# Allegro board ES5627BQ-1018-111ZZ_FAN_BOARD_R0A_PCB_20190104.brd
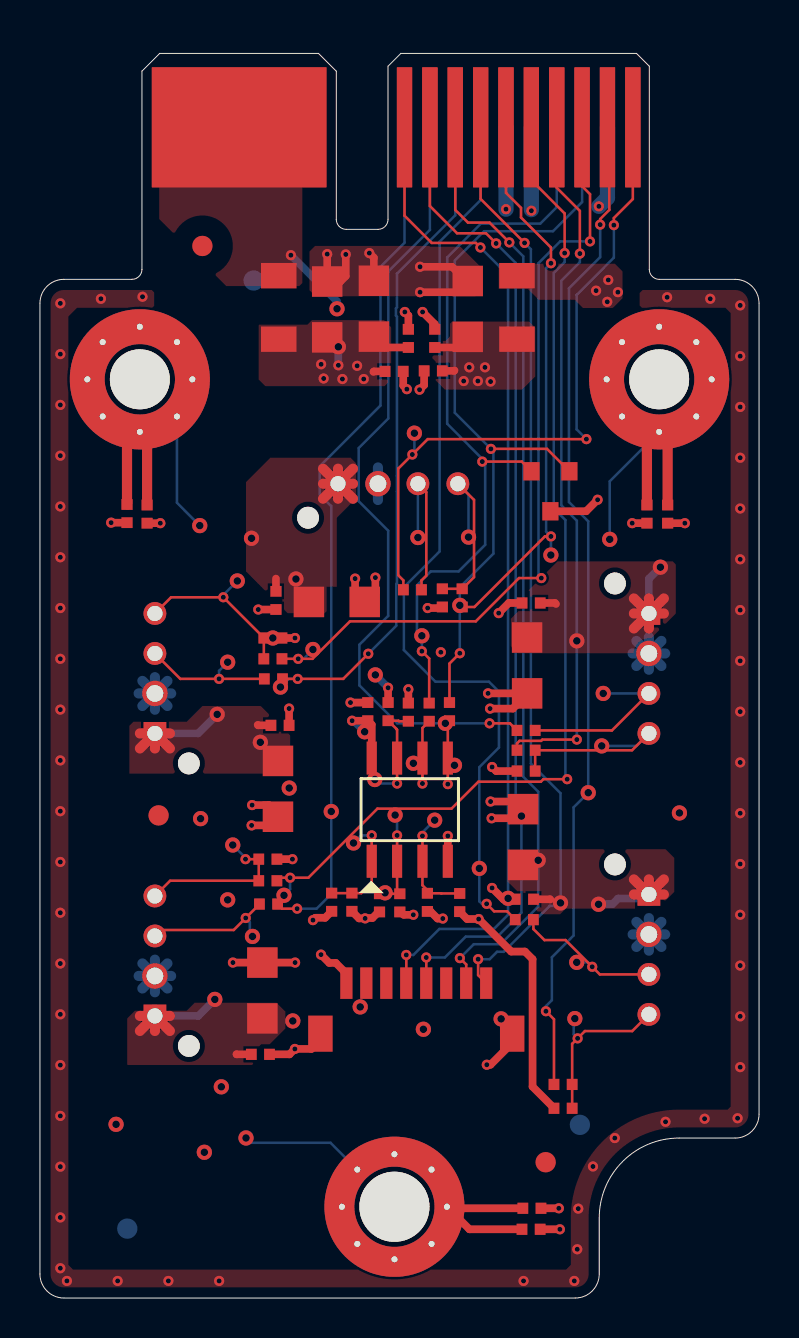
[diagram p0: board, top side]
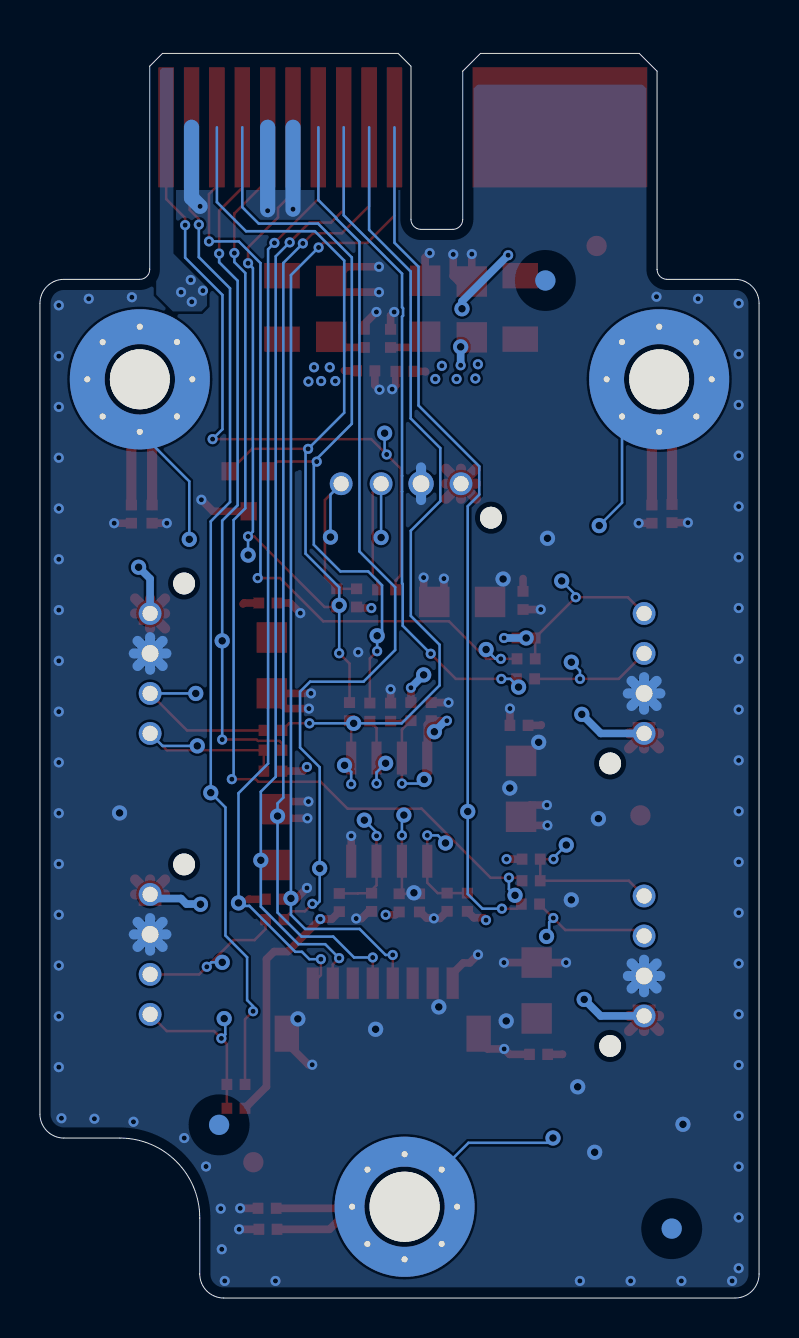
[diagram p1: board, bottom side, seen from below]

Outline 36 x 62.25 mm; copper layers: TOP, V2, G3, BOTTOM. Coordinates in mm from the lower left corner of the outline.
Outline path: 5.1,51.45 5.11,51.45 ; 5.11,51.45 arc(4.96,51.1) 4.61,50.95 1.2,50.95 arc(0.35,50.6) 0,49.75 0,1.2 arc(0.35,0.35) 1.2,0 26.8,0 arc(27.65,0.35) 28,1.2 28,4 arc(29.17,6.83) 32,8 34.8,8 arc(35.65,8.35) 36,9.2 36,49.75 arc(35.65,50.6) 34.8,50.95 31.01,50.95 arc(30.65,51.1) 30.51,51.45 30.51,61.61 29.87,62.25 18.06,62.25 17.43,61.61 17.43,53.95 arc(17.28,53.6) 16.93,53.45 15.33,53.45 arc(14.98,53.6) 14.84,53.95 14.84,61.36 13.95,62.25 6,62.25 5.11,61.36 5.11,51.45

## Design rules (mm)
nets with their own width: min track width 0.381; nets GND VCC3V3 VCC12V VCC_3V3

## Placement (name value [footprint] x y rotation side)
C1  0.1uF  [CC0402]  16.41 29.33 0 top
C2  10uF  [CC1206]  14.38 49.44 180 top
C3  10uF  [CC1206]  16.72 49.48 180 top
C5  0.1uF  [CC0402]  17.73 46.35 90 top
C6  0.1uF  [CC0402]  18.44 48 180 top
C7  10uF  [CC1206]  14.86 34.81 90 top
C9  0.1uF  [CC0402]  11.81 34.89 0 top
C10  10uF  [CC1206]  11.13 15.38 180 top
C12  0.1uF  [CC0402]  11.04 12.19 90 top
C13  10uF  [CC1206]  24.39 31.64 0 top
C15  0.1uF  [CC0402]  24.59 34.76 270 top
C16  10uF  [CC1206]  11.92 25.47 0 top
C18  0.1uF  [CC0402]  12.02 28.64 90 top
C19  10uF  [CC1206]  24.18 23.05 180 top
C21  0.1uF  [CC0402]  24.25 19.94 270 top
C22  10uF  [CC1206]  21.42 49.47 180 top
C25  0.1uF  [CC0402]  19.77 48 180 top
C26  0.1uF  [CC0402]  19.69 46.37 270 top
H1  SKREW 3mm  [MTH_276C118D_8DP_OSP]  31 45.95 0 top
H2  SKREW 3mm  [MTH_276C118D_8DP_OSP]  5 45.95 0 top
H3  SKREW 3.5mm  [MTH_276C138D_8DP_OSP]  17.75 4.56 0 top
J2  1-2232826-4  [CONN_2D_1X4DP_10D32W7D1L]  30.49 17.19 90 top
J3  1-2232826-4  [CONN_2D_1X4DP_10D32W7D1L]  5.75 31.24 270 top
J4  1-2232826-4  [CONN_2D_1X4DP_10D32W7D1L]  30.49 31.24 90 top
J5  1-2232826-4  [CONN_2D_1X4DP_10D32W7D1L]  5.75 17.11 270 top
J6  1-2232826-4  [CONN_2D_1X4DP_10D32W7D1L]  17.92 40.73 180 top
J7  1WFHK-08T-222  [CONN_1D_8SP_10W2D9L4D8H]  18.84 15.75 0 top
J8  @C214B5-100A  [GOLD_FINGER_1D27_10X2SP]  29.68 58.55 0 top
NOREF  -  []  6 62.25 0 top
NOREF#2  -  []  1.2 50.95 0 top
NOREF#3  -  []  0 0 0 top
NOREF#4  -  []  17.75 4.56 0 top
NOREF#5  -  []  0 0 0 top
NOREF#6  -  []  28 1.2 0 top
NOREF#7  -  [unnamed#2]  25.32 6.79 0 top
NOREF#8  -  [unnamed#2]  8.13 52.62 0 top
NOREF#9  -  []  5 45.95 0 top
NOREF#10  -  []  1.91 1.56 0 top
NOREF#11  -  []  31 45.95 0 top
NOREF#12  -  []  14.84 61.36 0 top
NOREF#13  -  []  31 45.95 0 top
NOREF#14  -  []  15.33 53.45 0 top
NOREF#15  -  []  17.75 4.56 0 top
NOREF#16  -  []  30.51 61.61 0 top
NOREF#17  -  []  36 9.2 0 top
NOREF#18  -  []  17.43 61.61 0 top
NOREF#19  -  []  5.11 61.36 0 top
NOREF#20  -  []  5 45.95 0 top
NOREF#21  -  [unnamed#2]  5.94 24.14 0 top
NOREF#22  -  []  199.5 -71.56 0 top
NOREF#23  -  [unnamed#2]  4.37 3.47 180 bottom
NOREF#24  -  [unnamed#2]  27.03 8.66 180 bottom
NOREF#25  -  []  19.88 46.93 90 bottom
NOREF#26  -  []  18.68 20.54 180 bottom
NOREF#27  -  [unnamed#2]  10.7 50.89 180 bottom
P5  PSOT03C  [SOT23_1D9X2D_3SP_1D3W2D92L1D11H]  25.55 40.35 180 top
R1  470ohm  [RC0402]  24.25 18.92 270 top
R6  1Kohm  [RC0402]  26.19 10.68 270 top
R7  470ohm  [RC0402]  11.69 30.97 90 top
R8  1Kohm  [RC0402]  11.66 31.97 90 top
R9  470ohm  [RC0402]  24.34 28.39 270 top
R10  1Kohm  [RC0402]  24.34 27.4 270 top
R11  470ohm  [RC0402]  11.44 19.7 90 top
R12  1Kohm  [RC0402]  11.41 20.87 90 top
R13  470ohm  [RC0402]  18.65 35.42 270 top
R14  1Kohm  [RC0402]  21.14 35.02 0 top
R15  @4.7Kohm  [RC0402]  14.6 19.8 0 top
R16  @4.7Kohm  [RC0402]  18.02 19.76 0 top
R17  @4.7Kohm  [RC0402]  21.01 19.78 0 top
R18  4.7Kohm  [RC0402]  15.62 19.8 180 top
R19  4.7Kohm  [RC0402]  17 19.76 180 top
R20  4.7Kohm  [RC0402]  19.4 19.79 180 top
R21  @4.7Kohm  [RC0402]  17.43 29.33 180 top
R22  4.7Kohm  [RC0402]  18.44 29.3 0 top
R23  0ohm  [RC0402]  19.49 29.3 0 top
R24  0ohm  [RC0402]  20.5 29.33 0 top
R25  0ohm  [RC0402]  31.42 39.21 0 top
R26  0ohm  [RC0402]  30.39 39.21 0 top
R27  0ohm  [RC0402]  4.36 39.23 0 top
R28  0ohm  [RC0402]  5.36 39.21 0 top
R29  0ohm  [RC0402]  24.63 4.49 90 top
R30  0ohm  [RC0402]  24.59 3.44 90 top
R31  0ohm  [RC1206]  11.95 49.55 180 top
R32  10Kohm  [RC0402]  26.19 9.49 270 top
R33  10Kohm  [RC0402]  11.66 33.01 90 top
R34  10Kohm  [RC0402]  24.34 26.36 270 top
R35  10Kohm  [RC0402]  11.41 21.95 90 top
R36  10Kohm  [RC0402]  20.15 35.02 0 top
R37  0ohm  [RC1206]  23.88 49.55 180 top
U1  AT24C02D-SSHM-T 2Kb  [SOIC_1D27X5D16_8SP_3D9W4D925L]  18.51 24.43 90 top

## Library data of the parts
C1-C3 C5-C7 C9 C10 C12 C13 C15 C16 C18 C19 C21 C22 C25 C26 = C_NP
H1-H3 = SKREW
J2-J6 = CONN_WAFER_MALE_4PX1R
J7 = CONN_WAFER_MALE_8PX1R_G2
J8 = C214B5-100A_0
P5 = TVS3_1
R1 R6-R37 = R: tolerance: 1%
U1 = EEPROM_ATMEL_AT24C02D

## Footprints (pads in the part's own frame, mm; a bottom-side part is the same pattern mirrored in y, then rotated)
CC0402
  rect 0.559x0.539 smd: 1(0,0.454) 2(0,-0.454)
CC1206
  rect 1.524x1.524 smd: 1(0,1.397) 2(0,-1.397)
CONN_1D_8SP_10W2D9L4D8H
  rect 0.61x1.575 smd: 1(3.5,0) 2(2.5,0) 3(1.5,0) 4(0.5,0) 5(-0.5,0) 6(-1.5,0) 7(-2.5,0) 8(-3.5,0)
  rect 1.219x1.803 smd: G1(-4.8,-2.525) G2(4.8,-2.525)
CONN_2D_1X4DP_10D32W7D1L
  round 1.092 hole 1.092 unplated: (4.5,1.7)
  rect 1.143x1.143 hole 0.762: 1(3,0)
  round 1.27 hole 0.838: 2(1,0)
  round 1.143 hole 0.762: 3(-1,0) 4(-3,0)
GOLD_FINGER_1D27_10X2SP
  rect 8.738x5.994 smd: P1A(-19.71,0) P1B(-19.71,0)
  rect 0.762x5.994 smd: S1(0,0) S2(-1.27,0) S3(-2.54,0) S4(-3.81,0) S5(-5.08,0) S6(-6.35,0) S7(-7.62,0) S8(-8.89,0) S9(-10.16,0) S10(-11.43,0) S11(0,0) S12(-1.27,0) S13(-2.54,0) S14(-3.81,0) S15(-5.08,0) S16(-6.35,0) S17(-7.62,0) S18(-8.89,0) S19(-10.16,0) S20(-11.43,0)
MTH_276C118D_8DP_OSP
  round 2.997 hole 2.997 unplated: (0,0)
  round 0.889 hole 0.305: 1(0,2.629) 2(1.859,1.859) 3(2.629,0) 4(1.859,-1.859) 5(0,-2.629) 6(-1.859,-1.859) 7(-2.629,0) 8(-1.859,1.859)
MTH_276C138D_8DP_OSP
  round 3.505 hole 3.505 unplated: (0,0)
  round 0.889 hole 0.305: 1(0,2.629) 2(1.859,1.859) 3(2.629,0) 4(1.859,-1.859) 5(0,-2.629) 6(-1.859,-1.859) 7(-2.629,0) 8(-1.859,1.859)
RC0402
  rect 0.559x0.539 smd: 1(0,0.454) 2(0,-0.454)
RC1206
  rect 1.778x1.27 smd: 1(0,1.587) 2(0,-1.587)
SOIC_1D27X5D16_8SP_3D9W4D925L
  rect 1.651x0.508 smd: 1(-2.58,1.905) 2(-2.58,0.635) 3(-2.58,-0.635) 4(-2.58,-1.905) 5(2.58,-1.905) 6(2.58,-0.635) 7(2.58,0.635) 8(2.58,1.905)
SOT23_1D9X2D_3SP_1D3W2D92L1D11H
  rect 0.813x0.914 smd: A(0,1) C1(-0.95,-1) C2(0.95,-1)
unnamed#2
  round 1.016 smd: (0,0)

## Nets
GND: C1.1 C2.2 C3.2 C5.2 C6.2 C7.2 C9.2 C10.2 C12.2 C13.2 C15.2 C16.2 C18.2 C19.2 C21.2 C22.2 C25.2 C26.2 J2.2 J3.2 J4.2 J5.2 J6.2 J7.8 J7.G1 J7.G2 J8.P1B J8.S2 J8.S5 J8.S6 P5.A R18.1 R19.1 R20.1 R22.1 R25.2 R26.2 R27.2 R28.2 R29.2 R30.2 U1.4(GND)
VCC3V3: C1.2 C22.1 C25.1 C26.1 R21.2 R37.1 U1.8(VCC)
VCC12V: C2.1 C3.1 C5.1 C6.1 C7.1 C9.1 C10.1 C12.1 C13.1 C15.1 C16.1 C18.1 C19.1 C21.1 J2.1 J3.1 J4.1 J5.1 J6.1 R31.1
VCC_3V3: J8.S1 R15.2 R16.2 R17.2 R32.2 R33.2 R34.2 R35.2 R36.2 R37.2
VCC_12V: J8.P1A R31.2
A0: R15.1 R18.2 U1.1(A0)
A1: R16.1 R19.2 U1.2(A1)
A2: R17.1 R20.2 U1.3(A2)
ALARM0_IN: J7.1 J8.S17
ALARM1_IN: J7.2 J8.S18
ALARM2_IN: J7.4 J8.S19
ALARM3_IN: J7.5 J8.S20
FAN_PWM0: J2.3 R1.1
FAN_PWM1: J3.3 R7.1
FAN_PWM2: J4.3 R9.1
FAN_PWM3: J5.3 R11.1
FAN_PWM4: J6.3 R13.1
FAN_TACH0: J2.4 R6.1 R32.1
FAN_TACH1: J3.4 R8.1 R33.1
FAN_TACH2: J4.4 R10.1 R34.1
FAN_TACH3: J5.4 R12.1 R35.1
FAN_TACH4: J6.4 R14.1 R36.1
I2C_CLK: J8.S4 P5.C2 R23.1
I2C_DAT: J8.S3 P5.C1 R24.1
PWM0: J8.S7 R1.2
PWM1: J8.S8 R7.2
PWM2: J8.S9 R9.2
PWM3: J8.S10 R11.2
PWM4: J8.S11 R13.2
TACH0: J8.S12 R6.2
TACH1: J8.S13 R8.2
TACH2: J8.S14 R10.2
TACH3: J8.S15 R12.2
TACH4: J8.S16 R14.2
N15562: R21.1 R22.2 U1.7(WP)
N15996: R23.2 U1.6(SCL)
N16000: R24.2 U1.5(SDA)
N16358: H1.1 H1.2 H1.3 H1.4 H1.5 H1.6 H1.7 H1.8 R25.1 R26.1
N20593: H2.1 H2.2 H2.3 H2.4 H2.5 H2.6 H2.7 H2.8 R27.1 R28.1
N20989: H3.1 H3.2 H3.3 H3.4 H3.5 H3.6 H3.7 H3.8 R29.1 R30.1

Pads without a net: J7 3 6 7

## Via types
v1: diameter 0.762, hole 0.381, TOP to BOTTOM, 59 vias
v2: diameter 0.508, hole 0.254, TOP to BOTTOM, 164 vias

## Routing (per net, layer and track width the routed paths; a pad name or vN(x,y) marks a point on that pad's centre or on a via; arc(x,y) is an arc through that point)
GND: length 131.2
  TOP w0.381: C18.2 v2(12.47,29.48) ; v2(14.07,17.17) 14.48,16.76 14.81,16.76 15.34,16.23 J7.8 ; R30.2 v2(26.03,3.44) ; R18.1 15.97,18.99 v2(16.28,18.99) 16.3,19.01 16.64,19.01 16.95,19.31 R19.1 ; v2(14.38,52.21) C2.2 15.04,50.84 15.31,51.11 v2(15.31,52.2) ; v2(27.92,39.93) 27.34,39.35 P5.A ; C9.2 v2(10.93,34.44) ; v2(12.77,16.78) C10.2 v2(9.66,16.78) ; C5.2 18.19,45.64 v2(18.37,45.46) ; C3.2 16.72,52.04 v2(16.49,52.26) ; v2(18.27,49.32) 18.44,49.14 C6.2 ; v2(19.16,49.32) 19.77,48.71 C25.2 ; 24.08,24.45 C19.2 ; 24.08,24.45 24.06,24.45 23.6,23.99 v2(22.61,23.99) ; 24.08,24.45 23.7,24.83 v2(22.56,24.83) ; C26.2 19.23,45.66 v2(19,45.43) ; U1.4 v2(20.42,23.11) ; R27.2 v2(3.56,38.78) ; R20.1 19.55,19.34 19.9,18.98 v2(20.17,18.98) ; v2(10.62,24.65) 11.46,24.65 11.92,24.2 C16.2 11.74,24.07 11.31,23.64 v2(10.6,23.64) ; J7.G2 23.64,12.75 22.56,11.67 v2(22.37,11.67) ; C15.2 23.47,34.76 v2(22.97,34.26) ; R26.2 v2(29.65,38.75) ; R25.2 v2(32.28,38.75) ; v2(22.43,30.24) C13.2 24.39,30.19 23.68,29.48 v2(22.53,29.48) ; R29.2 v2(25.98,4.49) ; R28.2 v2(6.03,38.75) ; v2(22.63,20.51) 23.2,19.94 C21.2 ; v2(19.03,50.31) 20.86,50.31 C22.2 21.34,50.87 20.63,51.58 v2(19.03,51.58) ; J7.G1 14.04,12.91 13.59,12.46 v2(12.76,12.46) 12.49,12.19 C12.2 ; v2(15.78,35.98) 15.78,35.25 16.21,34.81 C7.2 16.34,34.81 16.79,35.27 v2(16.79,36.03) ; C1.1 v2(15.55,29.78) ; R22.1 v2(18.44,30.45)
  G3 w0.508: J6.2 17.55,41.35 ; J6.2 16.92,41.54 ; J6.2 16.92,39.91 ; J6.2 17.55,40.1 ; J6.2 17.73,40.73 ; J6.2 16.3,40.1 ; J6.2 16.11,40.73 ; J6.2 16.3,41.35 ; 29.86,32.86 J4.2 ; J4.2 31.11,31.61 ; J4.2 31.3,32.24 ; J4.2 29.67,32.24 ; J4.2 30.49,33.05 ; J4.2 31.11,32.86 ; J4.2 30.49,31.43 ; J4.2 29.86,31.61 ; J3.2 6.38,30.86 ; J3.2 5.75,31.05 ; J3.2 6.57,30.24 ; J3.2 5.75,29.43 ; J3.2 4.94,30.24 ; J3.2 5.13,30.86 ; J3.2 6.38,29.61 ; J3.2 5.13,29.61 ; 29.86,17.56 J2.2 ; J2.2 31.11,17.56 ; J2.2 30.49,17.37 ; J2.2 31.11,18.81 ; J2.2 29.86,18.81 ; J2.2 29.67,18.19 ; J2.2 31.3,18.19 ; J2.2 30.49,19 ; J5.2 6.38,16.73 ; J5.2 5.75,15.29 ; J5.2 6.57,16.11 ; J5.2 4.94,16.11 ; J5.2 5.75,16.92 ; J5.2 6.38,15.48 ; J5.2 5.13,16.73 ; J5.2 5.13,15.48
  BOTTOM w0.381: v2(24.6,54.38) 24.6,54.44
  BOTTOM w0.508: J4.2 31.11,31.61 ; J4.2 30.49,31.43 ; J4.2 29.86,32.86 ; J4.2 29.86,31.61 ; J4.2 29.67,32.24 ; J4.2 31.3,32.24 ; J4.2 30.49,33.05 ; J4.2 31.11,32.86 ; 30.49,17.37 J2.2 ; J2.2 31.11,17.56 ; J2.2 31.11,18.81 ; J2.2 29.86,17.56 ; J2.2 30.49,19 ; J2.2 29.86,18.81 ; J2.2 31.3,18.19 ; J2.2 29.67,18.19 ; J3.2 5.75,31.05 ; J3.2 6.57,30.24 ; J3.2 4.94,30.24 ; J3.2 6.38,30.86 ; J3.2 5.13,29.61 ; J3.2 5.13,30.86 ; J3.2 6.38,29.61 ; J3.2 5.75,29.43 ; 5.13,16.73 J5.2 ; J5.2 6.57,16.11 ; J5.2 6.38,15.48 ; J5.2 5.75,15.29 ; J5.2 5.13,15.48 ; J5.2 6.38,16.73 ; J5.2 4.94,16.11 ; J5.2 5.75,16.92 ; 16.92,41.54 J6.2 16.92,39.91
  BOTTOM w0.762: v2(27.98,54.6) 28.41,55.03 J8.S2 ; 24.6,54.44 J8.S5 ; J8.S6 v2(23.33,54.46)
  vias: v1(3.81,8.69) v1(8.04,23.98) v1(8.23,7.29) v1(9.08,10.56) v1(9.4,19.91) v1(10.59,38) v1(11.03,27.79) v1(12.48,25.51) v1(12.66,13.86) v1(12.82,35.96) v1(16.03,14.56) v1(17.28,20.27) v1(19.2,13.44) v1(23.09,13.96) v1(32.01,24.26) v2(1.02,49.75) v2(1.02,47.21) v2(1.02,44.67) v2(1.02,42.13) v2(1.02,39.59) v2(1.02,37.05) v2(1.02,34.51) v2(1.02,31.97) v2(1.02,29.43) v2(1.02,26.89) v2(1.02,24.35) v2(1.02,21.81) v2(1.02,19.27) v2(1.02,16.73) v2(1.02,14.19) v2(1.02,11.65) v2(1.02,9.11) v2(1.02,6.57) v2(1.02,4.03) v2(1.02,1.49) v2(1.35,0.85) v2(3.05,49.98) v2(3.89,0.85) v2(5.13,50.08) v2(6.43,0.85) v2(8.97,0.85) v2(20.07,32.3) v2(24.21,0.85) v2(26.75,0.85) v2(26.95,4.47) v2(26.9,2.44) v2(27.69,6.58) v2(28.78,8) v2(31.32,8.81) v2(31.4,50.05) v2(33.27,8.97) v2(33.56,49.98) v2(34.92,8.99) v2(35.06,49.65) v2(35.06,47.11) v2(35.06,44.57) v2(35.06,42.03) v2(35.06,39.49) v2(35.06,36.95) v2(35.06,34.41) v2(35.06,31.87) v2(35.06,29.33) v2(35.06,26.79) v2(35.06,24.25) v2(35.06,21.71) v2(35.06,19.17) v2(35.06,16.63) v2(35.06,14.09) v2(35.06,11.55)
VCC3V3: length 7.7
  TOP w0.381: v2(15.63,28.87) C1.2 16.61,28.68 U1.8 ; C22.1 20.89,47.54 C25.1 ; R21.2 v2(17.43,30.52) ; 20.76,46.4 20.73,46.37 C26.1
  BOTTOM w0.381: v2(15.63,28.87) 15.7,28.87 v1(16.26,28.32) ; v2(17.43,30.52) 17.43,30.53 v1(16.79,31.17)
  vias: v2(21.21,45.86) v2(21.49,46.55) v2(21.92,45.86) v2(22.28,46.55) v2(22.56,45.84)
VCC12V: length 73.4
  TOP w0.381: 25.55,19.93 25.53,19.94 C21.1 ; 9.84,12.2 9.85,12.19 C12.1 ; C15.1 25.78,34.76 25.84,34.71 ; C3.1 17.26,47.54 C6.1 ; C18.1 10.93,28.64 10.9,28.67 ; 16.69,46.32 16.72,46.35 C5.1 ; C9.1 11.81,35.98
  TOP w0.508: 30.49,33.49 J4.1 ; J4.1 31.23,34.99 ; J4.1 30.49,34.99 ; J4.1 31.23,34.24 ; J4.1 29.74,34.99 ; J4.1 29.74,33.49 ; J4.1 29.74,34.24 ; J6.1 15.67,39.98 ; J6.1 15.67,41.48 ; J6.1 14.17,41.48 ; J6.1 14.17,39.98 ; J6.1 14.17,40.73 ; J6.1 15.67,40.73 ; J6.1 14.92,39.98 ; J6.1 14.92,41.48 ; 5.75,13.36 J5.1 ; J5.1 5.01,14.11 ; J5.1 6.5,14.11 ; J5.1 5.01,13.36 ; J5.1 6.5,13.36 ; 29.74,20.94 J2.1 ; J2.1 29.74,20.19 ; J2.1 31.23,20.94 ; J2.1 31.23,20.19 ; J2.1 30.49,20.94 ; 5.01,27.49 J3.1 ; J3.1 5.01,28.24 ; J3.1 6.5,27.49 ; J3.1 5.75,27.49 ; J3.1 6.5,28.24
  V2 w0.508: J2.1 31.07,19.61 ; J2.1 29.9,19.61 ; J2.1 29.74,20.19 ; J2.1 31.23,20.19 ; J2.1 30.49,20.94 ; J2.1 31.07,20.77 ; J2.1 29.9,20.77 ; J2.1 30.49,19.44 ; 29.9,33.66 J4.1 ; J4.1 31.23,34.24 ; J4.1 30.49,34.99 ; J4.1 30.49,33.49 ; J4.1 29.74,34.24 ; J4.1 29.9,34.82 ; J4.1 31.07,33.66 ; J4.1 31.07,34.82 ; J3.1 6.34,28.82 ; J3.1 5.17,27.66 ; J3.1 5.01,28.24 ; J3.1 6.5,28.24 ; J3.1 6.34,27.66 ; J3.1 5.75,27.49 ; J3.1 5.75,28.99 ; J3.1 5.17,28.82 ; J5.1 6.34,14.69 ; J5.1 5.17,13.53 ; J5.1 6.34,13.53 ; J5.1 6.5,14.11 ; J5.1 5.01,14.11 ; J5.1 5.75,14.86 ; J5.1 5.75,13.36 ; J5.1 5.17,14.69 ; 14.34,40.15 J6.1 ; J6.1 14.17,40.73 ; J6.1 14.34,41.31
  BOTTOM w0.381: J4.1 30.49,35.98 v1(31.06,36.55) ; v1(8.75,14.93) 7.93,14.11 J5.1 ; J2.1 30.28,19.98 28.94,19.98 28.66,19.71 27.98,19.71 v1(27.96,19.69) ; J3.1 7.92,28.24 v1(8.87,29.19) ; v1(14.94,47.57) v2(14.94,46.65)
  vias: v2(14.08,46.7) v2(14.2,45.99) v2(15.14,45.96) v2(15.88,46.63) v2(16.21,45.96)
VCC_3V3: length 19
  TOP w0.381: v2(19.41,34.51) 20.09,34.51 R36.2 ; R16.2 18.07,19.31 18.21,19.17 v2(18.69,19.17) ; R15.2 14.28,19.02 13.79,19.02 v2(13.67,18.9) ; R17.2 21.38,18.95 v2(21.96,18.95) 23.59,17.33 24.28,17.33 24.66,16.95 24.66,10.57 25.73,9.5 R32.2 ; R35.2 v2(12.64,21.95) ; R33.2 v2(12.77,33.01) ; R34.2 22.84,26.36 v2(22.64,26.56)
  BOTTOM w0.381: v2(12.77,33.01) v1(11.66,33.01)
  vias: v2(27.84,50.38) v2(28.4,49.83) v2(28.45,50.92) v2(28.93,50.31)
VCC_12V: length 3.6
  BOTTOM w0.381: v1(14.87,49.48) 14.87,49.85 v2(12.56,52.16)
A0: length 5.7
  TOP w0.127: R15.1 R18.2 16.09,20.25 16.61,20.77 U1.1 v2(16.61,23.14)
  BOTTOM w0.127: v1(15.7,22.76) 16.08,23.14 v2(16.61,23.14)
A1: length 5.1
  TOP w0.127: R19.2 R16.1 18.02,20.27 17.88,20.41 U1.2 v2(17.88,23.14)
  BOTTOM w0.127: v1(17.78,24.16) 17.88,24.06 v2(17.88,23.14)
A2: length 5.6
  TOP w0.127: R17.1 20.09,20.23 20.08,20.24 R20.2 19.4,20.4 19.15,20.64 U1.3 v2(19.15,23.11)
  BOTTOM w0.127: v1(19.76,23.9) 19.15,23.29 v2(19.15,23.11)
ALARM0_IN: length 47.1
  TOP w0.127: J8.S17 22.06,54.97 v2(24.26,52.77) ; J7.1 21.94,16.15 v2(21.94,16.95)
  BOTTOM w0.127: v2(24.26,52.77) 24.58,52.45 24.58,26.73 26.06,25.25 v1(26.06,19.76) 26.06,19.74 25.93,19.61 25.51,19.61 23.22,17.32 22.88,17.32 22.51,16.95 v2(21.94,16.95)
ALARM1_IN: length 47.7
  TOP w0.127: J7.2 21.34,16.68 v2(21.02,17) ; J8.S18 20.79,54.42 21.43,53.79 22.51,53.79 v2(23.5,52.8)
  BOTTOM w0.127: v2(21.02,17) 21.72,17.7 23.06,17.7 24.94,19.58 v1(24.94,21.89) 24.94,25.32 24.2,26.07 24.2,52.1 v2(23.5,52.8)
ALARM2_IN: length 49
  TOP w0.127: J8.S19 19.52,54.62 20.88,53.25 22.33,53.25 v2(22.84,52.75) ; v2(19.34,17.03) J7.4
  BOTTOM w0.127: v2(22.84,52.75) 23.82,51.77 23.82,25.03 24.1,24.74 v1(24.1,24.1) 24.1,19.28 22.9,18.08 21.32,18.08 20.27,17.03 v2(19.34,17.03)
ALARM3_IN: length 50.2
  TOP w0.127: v2(22.05,52.54) 21.82,52.77 19.61,52.77 18.25,54.13 J8.S20 ; v2(18.34,17.16) J7.5
  BOTTOM w0.127: v2(22.05,52.54) 23.44,51.16 v1(23.44,19.99) 23.44,19.17 22.73,18.46 20,18.46 18.7,17.16 v2(18.34,17.16)
FAN_PWM0: length 8.1
  TOP w0.127: R1.1 24.7,18.45 25.26,17.9 26.31,17.9 v2(27.65,16.57) 28.03,16.19 J2.3
  BOTTOM w0.127: v1(26.87,16.79) 27.42,16.79 v2(27.65,16.57)
FAN_PWM1: length 7
  TOP w0.127: R7.1 v2(8.97,30.97) 7.03,30.97 J3.3
  BOTTOM w0.127: v1(9.4,31.8) 8.97,31.37 v2(8.97,30.97)
FAN_PWM2: length 8.7
  TOP w0.127: R9.1 28.63,28.39 J4.3
  BOTTOM w0.127: J4.3 v1(28.2,30.24)
FAN_PWM3: length 7
  TOP w0.127: R11.1 10.99,19.69 v2(10.3,19.01) 9.7,18.41 6.05,18.41 J5.3
  BOTTOM w0.127: v2(10.3,19.01) 10.51,18.8 10.51,18.22 v1(10.64,18.08)
FAN_PWM4: length 8.3
  TOP w0.127: R13.1 19.1,35.89 19.34,36.13 19.34,40.31 J6.3
  BOTTOM w0.127: J6.3 v1(18.92,38.04)
FAN_TACH0: length 8.8
  TOP w0.127: J2.4 29.65,13.35 27.28,13.35 v2(26.92,12.99) 26.64,12.71 R6.1 R32.1
  BOTTOM w0.127: v2(26.92,12.99) 26.72,13.18 26.72,13.92 v1(26.78,13.98)
FAN_TACH1: length 8.8
  TOP w0.127: R8.1 R33.1 11.21,33.02 v2(9.18,35.05) 6.56,35.05 J3.4
  BOTTOM w0.127: v1(9.88,35.86) 9.18,35.16 v2(9.18,35.05)
FAN_TACH2: length 9.7
  TOP w0.127: R34.1 R10.1 29.64,27.4 J4.4
  BOTTOM w0.127: v1(28.12,27.61) 29.86,27.61 J4.4
FAN_TACH3: length 8.2
  TOP w0.127: v2(10.29,21.95) R35.1 R12.1 6.52,20.87 J5.4
  BOTTOM w0.127: v1(9.65,22.66) 10.29,22.02 v2(10.29,21.95)
FAN_TACH4: length 9.7
  TOP w0.127: J6.4 21.73,39.92 21.73,36.06 21.15,35.47 R14.1 R36.1
  BOTTOM w0.127: J6.4 20.92,40.71 21.46,40.18 v1(21.46,38.06)
I2C_CLK: length 38.7
  TOP w0.127: v2(22.14,41.83) 24.12,41.83 P5.C2 ; v2(19.12,32.35) 19.49,31.98 R23.1
  BOTTOM w0.127: J8.S4 25.87,54.56 25.05,53.74 22.08,53.74 20.39,52.05 20.39,43.73 22.14,41.97 v2(22.14,41.83) 22.29,41.69 22.29,37.67 20.96,36.34 19.56,36.34 18.87,35.65 18.87,33.37 v1(19.12,33.12) v2(19.12,32.35)
I2C_DAT: length 39.5
  TOP w0.127: R24.1 20.5,31.73 v2(21.02,32.25) ; v2(22.58,42.47) 25.38,42.47 P5.C1
  BOTTOM w0.127: J8.S3 27.14,54.81 25.68,53.36 22.24,53.36 20.77,51.89 20.77,44.28 v2(22.58,42.47) 22.7,42.34 22.7,37.23 21.02,35.55 v1(21.02,34.65) v2(21.02,32.25)
PWM0: length 46.4
  TOP w0.127: v2(22.36,19.72) 22.74,19.34 23.39,19.34 23.79,18.93 R1.2
  BOTTOM w0.127: J8.S7 22.06,54.92 21.17,54.03 21.17,54 20.01,52.83 20.01,37.34 18.22,35.55 18.22,32.41 19.8,30.83 22.48,30.83 22.98,30.32 22.98,27.53 22,26.55 v1(22,21.49) 22,19.84 22.12,19.72 v2(22.36,19.72)
PWM1: length 34
  TOP w0.127: R7.2 v2(12.9,30.97) 15.18,30.97 v2(16.44,32.22)
  BOTTOM w0.127: v2(16.44,32.22) 17.84,33.62 17.84,35.71 17.87,35.75 17.87,40.33 17.87,40.33 17.87,41.12 17.87,41.12 17.87,49.08 17.82,49.13 17.82,49.5 17.87,49.55 17.87,51.24 20.79,54.15 J8.S8 ; v1(12.04,30.56) 12.45,30.97 v2(12.9,30.97)
PWM2: length 39.4
  TOP w0.127: R9.2 23.53,28.74 v2(22.51,28.74)
  BOTTOM w0.127: v2(22.51,28.74) v1(20.29,28.74) 17.89,28.74 15.99,30.64 15.99,32.68 17.43,34.12 17.43,38.38 15.96,39.86 15.96,42.51 17.44,43.99 17.44,51.34 19.52,53.42 J8.S9
PWM3: length 43.4
  TOP w0.127: v2(12.87,19.47) 12.12,19.47 11.9,19.69 R11.2
  BOTTOM w0.127: J8.S10 18.25,52.78 17.05,51.58 17.05,44.64 14.01,41.6 14.01,40.18 14.58,39.61 v1(14.58,24.33) 14.58,20.21 13.85,19.47 v2(12.87,19.47)
PWM4: length 34.3
  TOP w0.127: R13.2 18.19,35.89 17.94,36.15 17.94,41.48 v2(18.64,42.19) 19.41,42.96 v2(27.36,42.96) ; J8.S11 29.68,54.97 28.73,54.02 v2(28.73,53.66)
  BOTTOM w0.127: v1(18.75,43.26) 18.75,42.29 v2(18.64,42.19) ; v2(28.73,53.66) 28.73,52.04 26.86,50.17 26.86,43.45 v2(27.36,42.96)
TACH0: length 50.2
  TOP w0.127: J8.S12 28.5,58.46 28.5,54.42 28.05,53.97 v2(28.05,53.69) ; v2(25.33,14.34) 25.73,13.94 R6.2
  BOTTOM w0.127: v2(28.05,53.69) 28.05,52.06 26.48,50.5 26.48,39.81 27.45,38.84 v1(27.45,25.27) 26.71,24.54 26.71,18.13 25.63,17.04 25.63,14.9 25.33,14.6 v2(25.33,14.34)
TACH1: length 40.3
  TOP w0.127: J8.S13 27.14,55.61 27.54,55.21 v2(27.54,52.85) ; v2(25.1,36.01) 23.98,36.01 21.82,33.85 15.52,33.85 13.64,31.97 v2(12.93,31.97) R8.2
  BOTTOM w0.127: v2(27.54,52.85) 26.05,52.85 24.96,51.76 24.96,36.15 v2(25.1,36.01) ; v1(13.67,32.44) 13.2,31.97 v2(12.93,31.97)
TACH2: length 35.2
  TOP w0.127: J8.S14 25.87,55.53 27.03,54.37 v2(27.03,52.24) ; R10.2 23.88,27.74 24.01,27.87 25.09,27.87 25.15,27.93 v2(26.88,27.93)
  BOTTOM w0.127: v2(26.88,27.93) v1(26.88,32.87) 26.88,38.88 26.1,39.65 26.1,50.88 27.03,51.81 v2(27.03,52.24)
TACH3: length 51.4
  TOP w0.127: R12.2 12.02,21.02 v2(12.52,21.02) 13.44,21.02 16.89,24.48 20.6,24.48 21.95,25.82 25.08,25.82 25.2,25.95 v2(26.39,25.95) ; v2(26.27,52.26) 26.27,54.25 24.6,55.91 J8.S15
  BOTTOM w0.127: v2(26.27,52.26) 26.27,51.81 25.72,51.27 25.72,39.49 26.31,38.91 26.31,26.04 v2(26.39,25.95) ; v2(12.52,21.02) 12.52,20.45 v1(12.22,20.14)
TACH4: length 28.4
  TOP w0.127: R14.2 21.75,34.56 25.28,38.09 v2(25.58,38.09) ; J8.S16 23.33,55.28 24.08,54.52 24.08,54.04 25.58,52.54 v2(25.58,51.76)
  BOTTOM w0.127: v1(25.58,37.16) 25.58,37.16 v2(25.58,38.09) 25.34,38.33 25.34,51.51 v2(25.58,51.76)
N15562: length 5.5
  TOP w0.127: v2(17.88,25.73) U1.7 17.88,28.42 17.84,28.46 17.84,28.47 17.44,28.87 ; R22.2 17.97,28.85 17.95,28.87 17.44,28.87 ; 17.44,28.87 R21.1
  BOTTOM w0.127: v2(17.88,25.73) 16.96,25.73 v1(16.76,25.93)
N15996: length 4.5
  TOP w0.127: v2(19.15,25.73) U1.6 19.15,28.51 R23.2
  BOTTOM w0.127: v1(18.69,26.75) 19.15,26.29 v2(19.15,25.73)
N16000: length 4.3
  TOP w0.127: R24.2 20.42,28.79 U1.5 v2(20.42,25.7)
  BOTTOM w0.127: v2(20.42,25.7) 20.42,26.31 v1(20.75,26.64)
N16358: length 14.1
  TOP w0.508: R26.1 30.39,42.71 H1.5 31.42,42.9 R25.1
  BOTTOM w0.127: H1.5 28.52,40.85 v1(28.52,37.95)
N20593: length 13.6
  TOP w0.508: R27.1 4.36,42.68 H2.5 5.36,42.96 R28.1
  BOTTOM w0.127: v1(8,38.63) 6.86,39.78 H2.4
N20989: length 14.2
  TOP w0.381: 20.45,4.49 21.5,3.44 R30.1 ; 20.45,4.49 H3.3 ; 20.45,4.49 R29.1
  BOTTOM w0.127: H3.8 14.55,7.76 10.56,7.76 v1(10.32,8)

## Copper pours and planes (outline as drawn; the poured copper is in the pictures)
GND on TOP: 1.2,0.53 0.73,0.73 0.53,1.2 0.53,49.75 0.73,50.22 1.2,50.42 4.61,50.42 4.64,50.42 5.59,50.42 5.72,50.29 5.72,49.63 5.62,49.53 4.66,49.53 4.61,49.53 1.86,49.53 1.42,49.09 1.42,1.66 1.66,1.42 26.34,1.42 26.58,1.66 26.58,4 28.17,7.83 32,9.42 34.43,9.42 34.58,9.57 34.58,49.27 34.32,49.53 31,49.53 30.95,49.53 30.14,49.53 30.02,49.64 30.02,50.27 30.17,50.42 30.97,50.42 31.01,50.42 34.8,50.42 35.27,50.22 35.47,49.75 35.47,9.2 35.27,8.73 34.8,8.53 32,8.53 28.79,7.21 27.47,4 27.47,1.2 27.27,0.73 26.8,0.53
GND on TOP: 13.77,52.62 21.01,52.62 22.08,51.55 22.08,50.38 21.8,50.11 13.8,50.11 13.49,50.41 13.49,52.34
GND on BOTTOM: 14.3,60.48 14.3,53.95 14.6,53.22 15.33,52.92 16.93,52.92 17.66,53.22 17.96,53.95 17.96,55.42 29.97,55.42 29.97,51.45 30.27,50.72 31.01,50.42 34.8,50.42 35.27,50.22 35.47,49.75 35.47,9.2 35.27,8.73 34.8,8.53 32,8.53 28.79,7.21 27.47,4 27.47,1.2 27.27,0.73 26.8,0.53 1.2,0.53 0.73,0.73 0.53,1.2 0.53,49.75 0.73,50.22 1.2,50.42 4.61,50.42 5.34,50.72 5.64,51.45 5.64,60.48 5.81,60.66 5.81,60.68 14.09,60.68 ; 21 cut-outs
GND on V2: 1.2,0.53 0.73,0.73 0.53,1.2 0.53,49.75 0.73,50.22 1.2,50.42 4.61,50.42 4.64,50.42 5.59,50.42 5.72,50.29 5.72,49.63 5.62,49.53 4.66,49.53 4.61,49.53 1.86,49.53 1.42,49.09 1.42,2.05 2.05,1.42 26.58,1.42 26.58,4 28.17,7.83 32,9.42 34.43,9.42 34.58,9.57 34.58,49.26 34.31,49.53 31,49.53 30.95,49.53 30.13,49.53 30.02,49.64 30.02,50.26 30.18,50.42 30.97,50.42 31.01,50.42 34.8,50.42 35.27,50.22 35.47,49.75 35.47,9.2 35.27,8.73 34.8,8.53 32,8.53 28.79,7.21 27.47,4 27.47,1.2 27.27,0.73 26.8,0.53
GND on G3: 6.22,61.72 13.72,61.72 14.3,61.14 14.3,53.95 14.6,53.22 15.33,52.92 16.93,52.92 17.66,53.22 17.96,53.95 17.96,61.39 18.29,61.72 29.64,61.72 29.97,61.39 29.97,51.45 30.27,50.72 31.01,50.42 34.8,50.42 35.27,50.22 35.47,49.75 35.47,9.2 35.27,8.73 34.8,8.53 32,8.53 28.79,7.21 27.47,4 27.47,1.2 27.27,0.73 26.8,0.53 1.2,0.53 0.73,0.73 0.53,1.2 0.53,49.75 0.73,50.22 1.2,50.42 4.61,50.42 5.34,50.72 5.64,51.45 5.64,61.14
VCC3V3 on TOP: 20.27,45.43 19.82,45.89 19.82,46.83 19.46,47.18 19.46,47.77 19.56,47.87 20.3,47.87 20.53,48.1 20.53,48.73 20.63,48.84 24.49,48.84 24.79,48.53 24.79,46.09 24.13,45.43
VCC3V3 on V2: 15.62,27.85 15.19,28.29 15.19,42.28 20.12,47.21 22.56,47.21 23.07,46.7 23.07,44.69 18.5,40.12 18.5,28.82 17.53,27.85
VCC12V on TOP: 10.98,48.68 13.39,48.68 13.62,48.91 17.23,48.91 17.58,48.56 17.58,45.94 17.25,45.61 11.28,45.61 10.95,45.94 10.95,48.66
VCC12V on TOP: 4.75,14.37 7.34,14.37 7.74,14.77 11.84,14.77 12.29,14.32 12.29,13.48 11.5,12.69 11.08,12.69 10.8,12.42 10.8,11.84 10.62,11.66 4.37,11.66 4.37,13.99
VCC12V on TOP: 4.68,28.82 7.34,28.82 8.13,29.61 11.05,29.61 12.53,28.13 12.53,26.53 12.22,26.23 4.47,26.23 4.47,28.62
VCC12V on TOP: 11.54,42.03 10.32,40.81 10.32,36.34 12.4,34.26 14.25,34.26 14.86,34.87 14.86,39.03 15.83,40 15.83,41.75 15.55,42.03
VCC12V on TOP: 24.54,35.35 24.54,34.94 23.58,33.98 23.58,32.6 23.93,32.25 29.85,32.25 31.83,34.23 31.83,36.69 31.68,36.85 25.91,36.85 24.46,35.4 24.51,35.35
VCC12V on TOP: 23.32,22.44 31.32,22.44 31.75,22.01 31.75,20.31 30.92,19.47 26.32,19.47 26.04,19.19 25.05,19.19 23.4,20.84 23.4,22.37
VCC12V on V2: 16.13,47.69 13.92,47.69 3.76,37.53 3.76,7.33 6.1,4.99 24.8,4.99 33.1,13.3 33.1,36.67 31.96,37.81 27.77,37.81 24.97,35.02 24.97,17.82 23.78,16.63 12.6,16.63 11.48,17.75 11.48,33.34 14.74,36.59 14.74,42.94 17.2,45.41 17.2,46.63
VCC_3V3 on TOP: 24.97,49.93 24.41,50.49 22.97,50.49 22.97,51.65 23.04,51.73 28.78,51.73 29.16,51.35 29.16,50 28.68,49.52 27.18,49.52 26.78,49.93
VCC_3V3 on BOTTOM: 27.92,49.34 27.64,49.62 27.64,50.56 29.32,52.24 29.32,61.48 29.37,61.54 29.86,61.54 30,61.4 30,51.45 30.04,51.15 30.18,50.87 30.18,50.18 29.34,49.34
VCC_3V3 on V2: 13.9,33.49 12.55,33.49 12.27,33.21 12.27,19.75 14.2,17.82 21.64,17.82 23.14,19.33 23.14,36.67 27.28,40.81 27.28,47.39 29.34,49.44 29.34,50.99 28.45,51.88 27.31,51.88 24.11,48.68 24.11,41.67 19.28,36.85 19.28,27.68 18.72,27.12 14.99,27.12 14.35,27.75 14.35,33.04
VCC_12V on TOP: 11.92,60.75 6.79,60.75 5.97,59.93 5.97,53.97 9.33,50.61 12.98,50.61 13.14,50.77 13.14,59.53
N16358 on TOP (solid shape): outline of 228 points within 27.5,42.45 34.5,49.45
N16358 on BOTTOM (solid shape): outline of 228 points within 27.5,42.45 34.5,49.45
N20593 on TOP (solid shape): outline of 228 points within 1.5,42.45 8.5,49.45
N20593 on BOTTOM (solid shape): outline of 228 points within 1.5,42.45 8.5,49.45
N20989 on TOP (solid shape): outline of 235 points within 14.24,1.06 21.25,8.07
N20989 on BOTTOM (solid shape): outline of 235 points within 14.24,1.06 21.25,8.07

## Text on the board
User.Comments: 62.25 [2.451] | 50.95 [2.006] | 36 [1.417] | dia7 [dia0.276] | dia3.5 [dia0.138] | dia3 [dia0.118] | dia9 [dia0.354]
Ref Des/Assembly Top: P/N:142000002194H REV:0A | B
DIMENSION: 5 | LinJing | 20181218 | 1 | ZONE | ROUGHNESS | ANGLE | PART NO. | MATERIAL | DESIGN | SCALE | UNIT | DIM. | 500 | 250 | 63 | 16 | 0 | GRADE | 1000 | 0.1 | 0.05 | . | 0.15 | 0.2 | 0.25 | 0.3 | 2 | 0.5 | 3 | 0.4 | 0.6 | 0.8 | 4 | 1.2 | 1.8 | 3.0 | FINISH. | MM | [IN] | This document and the | technical data disclosed | are proprietary to Accton | Tech. Corp. and shall not be | duplicated, used, released, | or disclosed without | expressed written permission. | OUTLINE-Corient_FAN-PCB | Reason | DESCRIPTION | UNSPECIFIED | TOL'S (+/-   mm) | +/- | DWG. TITLE | SHEET  / | REV. | SIZE | FMA-MD01001-02 R02 | 1deg | TECHNOLOGY CORP. | PCB T=1.6mm | A0 | A3 | 0 [0.000] | 62.25 [2.451] | 50.95 [2.006] | 28 [1.102] | 36 [1.417] | 8 [0.315] | R4 [R0.157] | 1.6 [0.063] | ∅7 [∅0.276] | ∅3.5 [∅0.138] | ∅3 [∅0.118] | ∅9 [∅0.354]
PAGE_OUTLINE: TOP | 1
TITLE_BOT: BOT | 4
User.5: V2 | 2
User.6: G3 | 3
User.7: SST | 5
User.8: SSB | 6
User.9: SMT | 7
User.10: SMB | 8
User.11: PMT | 9
User.12: PMB | 10
User.13: DRILL | 11
User.14: DIM | 12
User.15: FIGURE | SIZE | 10.0 | 12.0 | 30.0 | 33.0 | 43.0 | 118.0 | 138.0 | DRILL CHART: TOP to BOTTOM | ALL UNITS ARE IN MILS | TOLERANCE | +3.0/-3.0 | +2.0/-2.0 | PLATED | NON-PLATED | QTY | 164 | 24 | 15 | 5 | 2 | 1
